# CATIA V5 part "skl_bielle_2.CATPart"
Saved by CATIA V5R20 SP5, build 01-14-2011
Part number: skl_bielle_2
Publications: "Point.1", "Point.2", "Plan_ref", "Axe_pivot_bielle_2_exentrique", "Axe_pivot_bielle_2_bielle_3_4"
Bounding box of the stored display mesh (mm): x -10 to 10, y 0 to 0, z 0 to 100
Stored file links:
  U:\2A\IAO\ThinkMotion\skl_bielle_2.CATPart
  U:\2A\IAO\ThinkMotion\skl.CATProduct
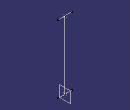
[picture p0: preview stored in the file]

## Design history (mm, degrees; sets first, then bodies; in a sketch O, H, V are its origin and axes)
Set1
  Point1: linked copy from another document
  Point2: linked copy from another document
  Plane1 "Plan_ref": linked copy from another document
Set2
  Line1: type PtPt, FirstPoint Point1, SecondPoint Point2
  Line2 "Axe_pivot_bielle_2_exentrique": type Normal, RefPoint Point1, RefSkin Plane1, Start -10, End 10
  Line3 "Axe_pivot_bielle_2_bielle_3_4": type Normal, RefPoint Point2, RefSkin Plane1, Start -10, End 10
Body1 (main body)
